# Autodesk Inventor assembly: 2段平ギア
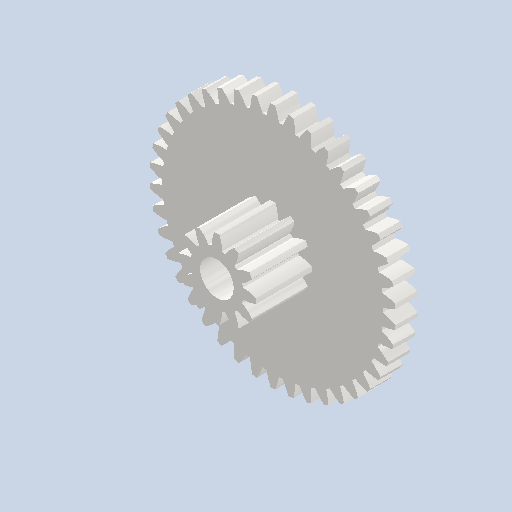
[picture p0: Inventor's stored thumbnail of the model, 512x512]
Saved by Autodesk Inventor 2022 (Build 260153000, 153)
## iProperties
Created: 2024-11
Part Number: 2段平ギア
Document SubType Name: Assembly
Designer: neo09
Author: neo09
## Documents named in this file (3)
- C:\Users\jsat7\OneDrive\デスクトップ\卒論2024\３DCAD\自在ギヤボックス\部品図\2段平ギア.iam
- C:\Users\jsat7\OneDrive\デスクトップ\卒論2024\３DCAD\自在ギヤボックス\部品図\42Tギア.ipt
- C:\Users\jsat7\OneDrive\デスクトップ\卒論2024\３DCAD\自在ギヤボックス\部品図\12Tギア　平ギア.ipt
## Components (2 placed, 1 different names)
1. 平歯車1:1 — リジッド:1
2. 平歯車1:2 — リジッド:1
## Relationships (1: WeldJoint 1)
- リジッド:1 [WeldJoint]: 平歯車1:1 ↔ 平歯車1:2
